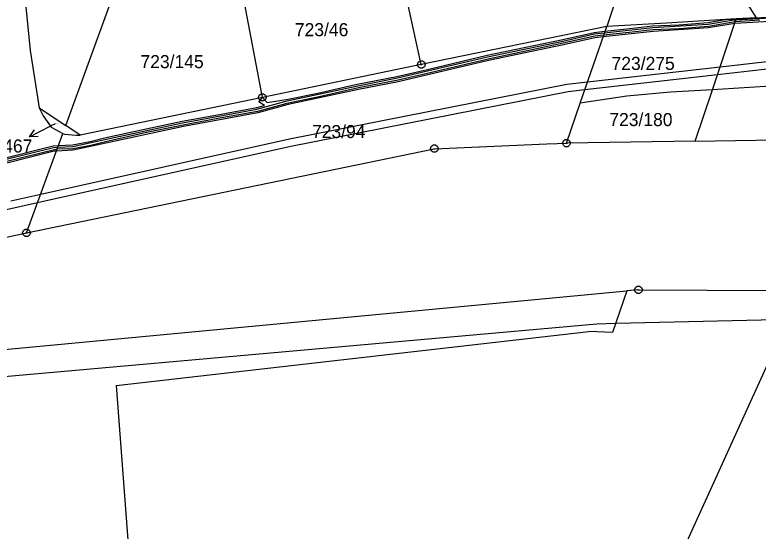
# Model space of a CAD drawing. Extents: x -759060 to -757386, y -1172273 to -1170948.
# Drawn here: x -757575.7 to -757479, y -1171174 to -1171106.8 of the extents above; entities that cross this region are included whole.
import ezdxf

# ---------------------------------------------------------------- set-up
doc = ezdxf.new("R2010")
doc.units = 0
for name, color, linetype in [('Vrstva 1', 7, 'Continuous'), ('Vrstva 11', 7, 'Continuous'), ('Vrstva 13', 7, 'Continuous'), ('Vrstva 2', 7, 'Continuous'), ('Vrstva 7', 7, 'Continuous'), ('Vrstva 8', 7, 'Continuous')]:
    doc.layers.add(name, color=color, linetype=linetype)

msp = doc.modelspace()

# ---------------------------------------------------------------- linework, layer by layer
at = {"layer": 'Vrstva 1'}
for p, q in [((-757543.51, -1171117.57), (-757549.23, -1171087.17)), ((-757479.25, -1171107.21), (-757491.57, -1171087.45)), ((-757493.67, -1171093.56), (-757498.73, -1171108.33)), ((-757522.84, -1171113.3), (-757525.16, -1171102.7)), ((-757574.36, -1171104.89), (-757573.73, -1171111.46)), ((-757569.08, -1171121.23), (-757563.26, -1171105.27)), ((-757481.88, -1171107.37), (-757490.96, -1171107.92)), ((-757484.97, -1171116.57), (-757481.88, -1171107.37)), ((-757479.25, -1171107.21), (-757481.88, -1171107.37)), ((-757479.25, -1171107.21), (-757474.76, -1171106.93)), ((-757498.73, -1171108.33), (-757522.84, -1171113.3)), ((-757502.17, -1171118.34), (-757498.73, -1171108.33)), ((-757490.96, -1171107.92), (-757498.73, -1171108.33)), ((-757573.73, -1171111.46), (-757572.53, -1171118.93)), ((-757522.84, -1171113.3), (-757543.51, -1171117.57)), ((-757474.22, -1171115.92), (-757484.97, -1171116.57)), ((-757496.12, -1171117.4), (-757502.17, -1171118.34)), ((-757490.41, -1171116.9), (-757496.12, -1171117.4)), ((-757484.97, -1171116.57), (-757490.41, -1171116.9)), ((-757487.21, -1171123.27), (-757484.97, -1171116.57)), ((-757543.51, -1171117.57), (-757567.21, -1171122.47)), ((-757503.95, -1171123.53), (-757502.17, -1171118.34)), ((-757572.53, -1171118.93), (-757572, -1171119.96)), ((-757572.53, -1171118.93), (-757569.08, -1171121.23)), ((-757572, -1171119.96), (-757570.99, -1171121.47)), ((-757567.21, -1171122.47), (-757569.08, -1171121.23)), ((-757570.99, -1171121.47), (-757569.46, -1171122.26)), ((-757574.18, -1171135.22), (-757569.46, -1171122.26)), ((-757569.46, -1171122.26), (-757569.25, -1171122.37)), ((-757569.25, -1171122.37), (-757567.74, -1171122.48)), ((-757567.74, -1171122.48), (-757567.21, -1171122.47)), ((-757487.21, -1171123.27), (-757471.52, -1171123.03)), ((-757521.15, -1171124.25), (-757506.5, -1171123.64)), ((-757506.5, -1171123.64), (-757505.18, -1171123.58)), ((-757505.18, -1171123.58), (-757503.95, -1171123.53)), ((-757487.21, -1171123.27), (-757503.95, -1171123.53)), ((-757574.18, -1171135.22), (-757521.15, -1171124.25)), ((-757635.32, -1171148.1), (-757575.38, -1171135.47)), ((-757575.38, -1171135.47), (-757574.18, -1171135.22)), ((-757578.4, -1171150.51), (-757496.1, -1171142.77)), ((-757496.1, -1171142.77), (-757497.96, -1171148.17)), ((-757494.59, -1171142.63), (-757496.1, -1171142.77)), ((-757494.59, -1171142.63), (-757473.48, -1171142.7)), ((-757473.48, -1171142.7), (-757494.18, -1171188.26)), ((-757562.52, -1171155.07), (-757501.07, -1171148.04)), ((-757497.96, -1171148.17), (-757501.07, -1171148.04)), ((-757562.52, -1171155.07), (-757555.07, -1171253.96))]:
    msp.add_line(p, q, dxfattribs=at)
at = {"layer": 'Vrstva 11'}
for p, q in [((-757577.57, -1171153.95), (-757500, -1171147.04)), ((-757500, -1171147.04), (-757497.55, -1171146.98)), ((-757497.55, -1171146.98), (-757475.17, -1171146.43))]:
    msp.add_line(p, q, dxfattribs=at)
at = {"layer": 'Vrstva 13'}
for p, q in [((-757485.56, -1171107.84), (-757483.26, -1171107.45)), ((-757485.54, -1171108.04), (-757482.18, -1171107.47)), ((-757483.26, -1171107.45), (-757479.25, -1171107.21)), ((-757482.18, -1171107.47), (-757481.91, -1171107.46)), ((-757475.75, -1171107.62), (-757482.08, -1171107.97)), ((-757478.81, -1171107.51), (-757482.01, -1171107.76)), ((-757481.91, -1171107.46), (-757475.81, -1171107.12)), ((-757479.25, -1171107.21), (-757474.76, -1171106.93)), ((-757499.02, -1171109.17), (-757492.74, -1171108.48)), ((-757498.95, -1171108.96), (-757495.72, -1171108.62)), ((-757495.72, -1171108.62), (-757492.75, -1171108.28)), ((-757492.75, -1171108.28), (-757489.31, -1171108.14)), ((-757492.74, -1171108.48), (-757485.54, -1171108.04)), ((-757489.31, -1171108.64), (-757492.73, -1171108.78)), ((-757485.48, -1171108.54), (-757492.7, -1171108.98)), ((-757489.31, -1171108.14), (-757485.56, -1171107.84)), ((-757485.5, -1171108.34), (-757489.31, -1171108.64)), ((-757482.01, -1171107.76), (-757485.5, -1171108.34)), ((-757482.08, -1171107.97), (-757485.48, -1171108.54)), ((-757504.44, -1171110.03), (-757500.36, -1171109.11)), ((-757504.43, -1171110.24), (-757500.33, -1171109.31)), ((-757500.28, -1171109.61), (-757504.4, -1171110.53)), ((-757500.36, -1171109.11), (-757498.95, -1171108.96)), ((-757500.33, -1171109.31), (-757499.02, -1171109.17)), ((-757499.13, -1171109.49), (-757500.28, -1171109.61)), ((-757492.7, -1171108.98), (-757499.2, -1171109.7)), ((-757495.79, -1171109.14), (-757499.13, -1171109.49)), ((-757492.73, -1171108.78), (-757495.79, -1171109.14)), ((-757514.22, -1171112.29), (-757504.43, -1171110.24)), ((-757509.48, -1171111.1), (-757504.44, -1171110.03)), ((-757504.4, -1171110.53), (-757509.24, -1171111.56)), ((-757500.25, -1171109.81), (-757504.33, -1171110.72)), ((-757499.2, -1171109.7), (-757500.25, -1171109.81)), ((-757514.26, -1171112.08), (-757509.48, -1171111.1)), ((-757509.24, -1171111.56), (-757514.16, -1171112.58)), ((-757504.33, -1171110.72), (-757514.12, -1171112.77)), ((-757525.94, -1171115.05), (-757514.22, -1171112.29)), ((-757514.16, -1171112.58), (-757522.24, -1171114.49)), ((-757522.04, -1171113.93), (-757514.26, -1171112.08)), ((-757483.97, -1171113.6), (-757468.49, -1171111.85)), ((-757514.12, -1171112.77), (-757525.84, -1171115.53)), ((-757468.29, -1171112.83), (-757484.32, -1171114.64)), ((-757526.01, -1171114.85), (-757522.04, -1171113.93)), ((-757522.24, -1171114.49), (-757525.85, -1171115.33)), ((-757501.21, -1171115.54), (-757483.97, -1171113.6)), ((-757531.16, -1171115.85), (-757526.01, -1171114.85)), ((-757531.1, -1171116.05), (-757525.94, -1171115.05)), ((-757525.85, -1171115.33), (-757531.02, -1171116.33)), ((-757484.32, -1171114.64), (-757501.57, -1171116.59)), ((-757540.28, -1171118.04), (-757531.1, -1171116.05)), ((-757540, -1171122.98), (-757503.9, -1171115.85)), ((-757536.28, -1171117.03), (-757531.16, -1171115.85)), ((-757531.02, -1171116.33), (-757536.14, -1171117.51)), ((-757525.84, -1171115.53), (-757531, -1171116.54)), ((-757503.9, -1171115.85), (-757501.21, -1171115.54)), ((-757531, -1171116.54), (-757540.16, -1171118.52)), ((-757540.15, -1171117.81), (-757536.28, -1171117.03)), ((-757503.74, -1171116.83), (-757539.8, -1171123.96)), ((-757501.57, -1171116.59), (-757503.74, -1171116.83)), ((-757544.22, -1171119.11), (-757540.28, -1171118.04)), ((-757540.33, -1171118.36), (-757544.15, -1171119.4)), ((-757543.99, -1171118.14), (-757543.51, -1171117.57)), ((-757543.22, -1171118.63), (-757543.99, -1171118.14)), ((-757543.51, -1171117.57), (-757542.9, -1171118.24)), ((-757542.9, -1171118.24), (-757540.15, -1171117.81)), ((-757536.14, -1171117.51), (-757540.33, -1171118.36)), ((-757553.88, -1171120.89), (-757544.22, -1171119.11)), ((-757549.58, -1171119.88), (-757544.25, -1171118.9)), ((-757544.25, -1171118.9), (-757543.22, -1171118.63)), ((-757540.16, -1171118.52), (-757544.11, -1171119.59)), ((-757553.92, -1171120.68), (-757549.58, -1171119.88)), ((-757544.11, -1171119.59), (-757553.78, -1171121.38)), ((-757544.15, -1171119.4), (-757549.29, -1171120.34)), ((-757563.98, -1171123.06), (-757553.88, -1171120.89)), ((-757558.62, -1171121.66), (-757553.92, -1171120.68)), ((-757553.82, -1171121.18), (-757558.56, -1171122.16)), ((-757549.29, -1171120.34), (-757553.82, -1171121.18)), ((-757564.05, -1171122.86), (-757558.62, -1171121.66)), ((-757558.56, -1171122.16), (-757563.91, -1171123.34)), ((-757553.78, -1171121.38), (-757563.88, -1171123.54)), ((-757572.34, -1171130.18), (-757540, -1171122.98)), ((-757568.18, -1171123.96), (-757563.98, -1171123.06)), ((-757565.92, -1171123.32), (-757564.05, -1171122.86)), ((-757577.08, -1171125.48), (-757570.7, -1171123.89)), ((-757577.02, -1171125.68), (-757570.67, -1171124.09)), ((-757539.8, -1171123.96), (-757572.75, -1171131.29)), ((-757570.7, -1171123.89), (-757570.03, -1171123.83)), ((-757570.67, -1171124.09), (-757570.12, -1171124.06)), ((-757570.12, -1171124.06), (-757568.18, -1171123.96)), ((-757570.03, -1171123.83), (-757568.2, -1171123.76)), ((-757568.2, -1171123.76), (-757565.92, -1171123.32)), ((-757565.82, -1171123.82), (-757568.14, -1171124.26)), ((-757563.88, -1171123.54), (-757568.12, -1171124.46)), ((-757563.91, -1171123.34), (-757565.82, -1171123.82)), ((-757570.21, -1171124.33), (-757576.92, -1171125.96)), ((-757570.59, -1171124.59), (-757576.9, -1171126.16)), ((-757570.3, -1171124.58), (-757570.59, -1171124.59)), ((-757568.12, -1171124.46), (-757570.3, -1171124.58)), ((-757568.14, -1171124.26), (-757570.21, -1171124.33)), ((-757576.21, -1171131.04), (-757572.34, -1171130.18)), ((-757572.75, -1171131.29), (-757577.01, -1171132.24))]:
    msp.add_line(p, q, dxfattribs=at)
at = {"layer": 'Vrstva 7'}
for p in [(-757570.44, -1171121), (-757573.8, -1171122.688)]:
    msp.add_line(p, (-757571.12, -1171121.34), dxfattribs=at)
msp.add_lwpolyline([(-757572.682, -1171122.686), (-757573.8, -1171122.688), (-757573.131, -1171121.792)], dxfattribs=at)
at = {"layer": 'Vrstva 8'}
for p, q in [((-757522.96, -1171113.3), (-757522.72, -1171113.3)), ((-757543.63, -1171117.57), (-757543.39, -1171117.57)), ((-757504.07, -1171123.53), (-757503.83, -1171123.53)), ((-757521.27, -1171124.25), (-757521.03, -1171124.25)), ((-757574.3, -1171135.22), (-757574.06, -1171135.22)), ((-757494.71, -1171142.63), (-757494.47, -1171142.63))]:
    msp.add_line(p, q, dxfattribs=at)
for points in [[(-757522.69, -1171112.82), (-757522.44, -1171113), (-757522.34, -1171113.29), (-757522.44, -1171113.58), (-757522.69, -1171113.76), (-757523, -1171113.76), (-757523.25, -1171113.58), (-757523.35, -1171113.29), (-757523.25, -1171113), (-757523, -1171112.82)], [(-757543.36, -1171117.09), (-757543.11, -1171117.27), (-757543.01, -1171117.56), (-757543.11, -1171117.85), (-757543.36, -1171118.03), (-757543.67, -1171118.03), (-757543.92, -1171117.85), (-757544.02, -1171117.56), (-757543.92, -1171117.27), (-757543.67, -1171117.09)], [(-757503.8, -1171123.05), (-757503.55, -1171123.23), (-757503.45, -1171123.52), (-757503.55, -1171123.81), (-757503.8, -1171123.99), (-757504.11, -1171123.99), (-757504.36, -1171123.81), (-757504.46, -1171123.52), (-757504.36, -1171123.23), (-757504.11, -1171123.05)], [(-757521, -1171123.77), (-757520.75, -1171123.95), (-757520.65, -1171124.24), (-757520.75, -1171124.53), (-757521, -1171124.71), (-757521.31, -1171124.71), (-757521.56, -1171124.53), (-757521.66, -1171124.24), (-757521.56, -1171123.95), (-757521.31, -1171123.77)], [(-757574.03, -1171134.74), (-757573.78, -1171134.92), (-757573.68, -1171135.21), (-757573.78, -1171135.5), (-757574.03, -1171135.68), (-757574.34, -1171135.68), (-757574.59, -1171135.5), (-757574.69, -1171135.21), (-757574.59, -1171134.92), (-757574.34, -1171134.74)], [(-757494.44, -1171142.15), (-757494.19, -1171142.33), (-757494.09, -1171142.62), (-757494.19, -1171142.91), (-757494.44, -1171143.09), (-757494.75, -1171143.09), (-757495, -1171142.91), (-757495.1, -1171142.62), (-757495, -1171142.33), (-757494.75, -1171142.15)]]:
    msp.add_lwpolyline(points, close=True, dxfattribs=at)

# ---------------------------------------------------------------- texts
at = {"layer": 'Vrstva 2'}
for s, height, p in [('723/46', 1.7, (-757539.283, -1171109.61)), ('723/145', 1.7, (-757559.361, -1171113.77)), ('723/275', 1.7, (-757498.093, -1171114)), ('723/180', 1.7, (-757498.383, -1171121.31)), ('723/467', 0.1, (-757570.426, -1171121)), ('723/94', 1.7, (-757537.053, -1171122.87))]:
    msp.add_text(s, height=height, dxfattribs=at).set_placement(p)
at = {"layer": 'Vrstva 7'}
msp.add_text('723/467', height=1.7, dxfattribs=at).set_placement((-757581.642, -1171124.75))

doc.saveas('drawing.dxf')
